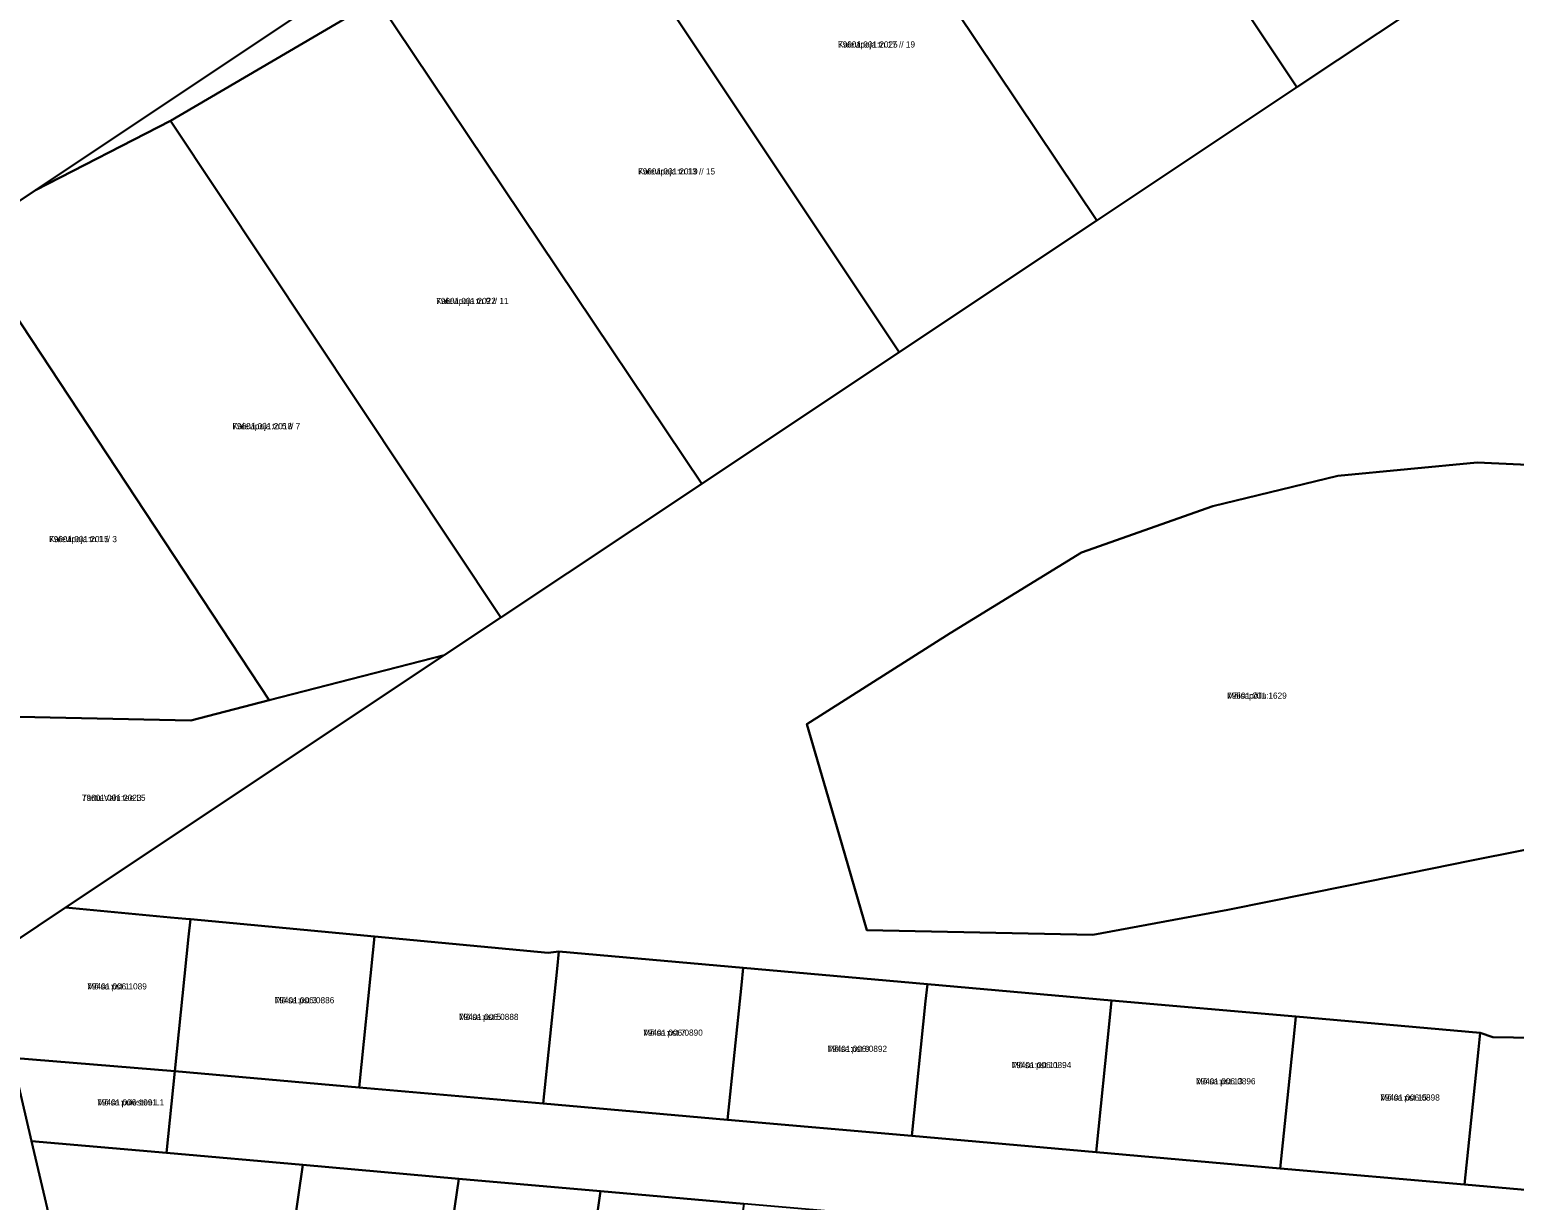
# Model space of a CAD drawing. Extents: x 625111 to 706696, y 6474150 to 6504223.
# Drawn here: x 659027.1 to 659388.4, y 6477250.5 to 6477535.3 of the extents above; entities that cross this region are included whole.
import ezdxf

# ---------------------------------------------------------------- set-up
doc = ezdxf.new("R2010")
doc.units = 0
for name, color, linetype in [('L_AADRESS', 7, 'Continuous'), ('PIIR', 7, 'Continuous'), ('TUNNUS', 7, 'Continuous')]:
    doc.layers.add(name, color=color, linetype=linetype)

msp = doc.modelspace()

# ---------------------------------------------------------------- linework, layer by layer
at = {"layer": 'PIIR'}
for points in [[(659232.49, 6477793.03), (659251.76, 6477778.82), (659253.39, 6477777.62), (659345.56, 6477707.61), (659341.25, 6477704.74), (659028.54, 6477496.24), (659011.15, 6477484.64), (658978.33, 6477462.76), (658893.64, 6477716.85), (658906.78, 6477751.79), (658969.42, 6477781.01), (659162.31, 6477839.01), (659167.55, 6477840.54), (659168.77, 6477839.47), (659176.76, 6477833.75), (659193.86, 6477821.51)], [(659028.54, 6477496.24), (659341.25, 6477704.74), (659345.56, 6477707.61), (659353.33, 6477701.7), (659348.84, 6477698.71), (659339.23, 6477692.3), (659307.13, 6477670.9), (659257.71, 6477637.96), (659208.73, 6477605.29), (659160.85, 6477573.67), (659111.66, 6477542.61), (659061.4, 6477513.14)], [(659257.71, 6477637.96), (659307.13, 6477670.9), (659384.93, 6477554.2), (659335.49, 6477521.28)], [(659208.73, 6477605.29), (659257.71, 6477637.96), (659335.49, 6477521.28), (659286.78, 6477488.84)], [(659160.85, 6477573.67), (659208.73, 6477605.29), (659286.78, 6477488.84), (659238.68, 6477456.8)], [(659111.66, 6477542.61), (659160.85, 6477573.67), (659238.68, 6477456.8), (659190.69, 6477424.84)], [(659061.4, 6477513.14), (659111.66, 6477542.61), (659190.69, 6477424.84), (659141.77, 6477392.27)], [(659011.15, 6477484.64), (659028.54, 6477496.24), (659061.4, 6477513.14), (659141.77, 6477392.27), (659128, 6477383.1), (659085.37, 6477372.16)], [(658978.33, 6477462.76), (659011.15, 6477484.64), (659085.37, 6477372.16), (659066.32, 6477367.26), (659016.87, 6477368.25), (659003.37, 6477387.46)], [(659216.21, 6477366.34), (659224.06, 6477339.44), (659230.84, 6477316.19), (659285.85, 6477315.08), (659318.68, 6477321.16), (659348.02, 6477327.11), (659377.96, 6477333.14), (659401.27, 6477337.81), (659406.94, 6477338.94), (659417.81, 6477428.24), (659412.69, 6477428.47), (659379.35, 6477429.97), (659345.4, 6477426.74), (659315.02, 6477419.4), (659283.04, 6477408.07), (659251.14, 6477388.49)], [(659224.06, 6477339.44), (659216.21, 6477366.34), (659251.14, 6477388.49), (659283.04, 6477408.07), (659315.02, 6477419.4), (659345.4, 6477426.74), (659379.35, 6477429.97), (659412.69, 6477428.47), (659417.81, 6477428.24), (659406.94, 6477338.94), (659401.27, 6477337.81), (659377.96, 6477333.14), (659348.02, 6477327.11), (659318.68, 6477321.16), (659285.85, 6477315.08), (659230.84, 6477316.19)], [(659035.81, 6477321.69), (659015.77, 6477308.37), (659002.48, 6477356.08), (658992.28, 6477386.97), (659016.87, 6477368.25), (659066.32, 6477367.26), (659085.37, 6477372.16), (659128, 6477383.1)], [(659065.79, 6477314.62), (659062.43, 6477281.9), (659022.88, 6477285.14), (659015.77, 6477308.37), (659035.81, 6477321.69), (659061.4, 6477319.31), (659065.14, 6477318.97), (659066.23, 6477318.87)], [(659110.63, 6477310.69), (659107.27, 6477277.96), (659062.43, 6477281.9), (659065.79, 6477314.62), (659066.23, 6477318.87), (659076.62, 6477317.94), (659111.03, 6477314.7)], [(659155.46, 6477306.77), (659152.1, 6477274.02), (659107.27, 6477277.96), (659110.63, 6477310.69), (659111.03, 6477314.7), (659153.27, 6477310.72), (659155.9, 6477310.99)], [(659200.3, 6477302.85), (659196.93, 6477270.08), (659152.1, 6477274.02), (659155.46, 6477306.77), (659155.9, 6477310.99), (659200.73, 6477307.06)], [(659245.13, 6477298.92), (659241.76, 6477266.14), (659196.93, 6477270.08), (659200.3, 6477302.85), (659200.73, 6477307.06), (659245.57, 6477303.09)], [(659289.96, 6477295), (659286.59, 6477262.2), (659241.76, 6477266.14), (659245.13, 6477298.92), (659245.57, 6477303.09), (659290.38, 6477299.14)], [(659334.8, 6477291.08), (659331.43, 6477258.26), (659286.59, 6477262.2), (659289.96, 6477295), (659290.38, 6477299.14), (659335.23, 6477295.17)], [(659379.63, 6477287.15), (659376.26, 6477254.32), (659331.43, 6477258.26), (659334.8, 6477291.08), (659335.23, 6477295.17), (659380.03, 6477291.23)], [(659415.36, 6477283.25), (659410.25, 6477251.33), (659376.26, 6477254.32), (659379.63, 6477287.15), (659380.03, 6477291.23), (659383.12, 6477290.18), (659393.2, 6477290.01), (659400.9, 6477289.36), (659416.13, 6477288.02)], [(659062.43, 6477281.9), (659060.39, 6477262), (659027.61, 6477264.87), (659022.88, 6477285.14)], [(659093.63, 6477259.08), (659088.92, 6477226.55), (659034.62, 6477234.89), (659027.61, 6477264.87), (659060.39, 6477262)], [(659131.55, 6477255.75), (659126.48, 6477220.78), (659088.92, 6477226.55), (659093.63, 6477259.08)], [(659166.04, 6477252.72), (659160.66, 6477215.53), (659126.48, 6477220.78), (659131.55, 6477255.75)], [(659200.88, 6477249.65), (659195.17, 6477210.23), (659160.66, 6477215.53), (659166.04, 6477252.72)]]:
    msp.add_lwpolyline(points, close=True, dxfattribs=at)
for points in [[(659393.2, 6477290.01), (659383.12, 6477290.18), (659380.03, 6477291.23), (659335.23, 6477295.17), (659290.38, 6477299.14), (659245.57, 6477303.09), (659200.73, 6477307.06), (659155.9, 6477310.99), (659153.27, 6477310.72), (659111.03, 6477314.7), (659076.62, 6477317.94), (659066.23, 6477318.87), (659065.14, 6477318.97), (659061.4, 6477319.31), (659035.81, 6477321.69), (659128, 6477383.1), (659141.77, 6477392.27), (659190.69, 6477424.84), (659238.68, 6477456.8), (659286.78, 6477488.84), (659335.49, 6477521.28), (659384.93, 6477554.2)], [(659022.88, 6477285.14), (659027.61, 6477264.87), (659034.62, 6477234.89), (659046.22, 6477185.21), (659054.92, 6477147.94), (659058.14, 6477134.15), (659072.57, 6477072.34), (659083.27, 6477026.56), (659093.96, 6476980.77), (659119.09, 6476873.18), (659130.63, 6476823.75), (659145.22, 6476761.27), (659156.03, 6476714.99), (659137.78, 6476720.47), (659111.23, 6476832.81), (659041.31, 6477128.02), (659034.25, 6477157.62), (659034.75, 6477157.58), (659008.22, 6477269.11)], [(659407.08, 6477231.53), (659377.48, 6477234.13), (659349.54, 6477236.59), (659321.6, 6477239.04), (659292.67, 6477241.59), (659262.74, 6477244.22), (659231.81, 6477246.94), (659200.88, 6477249.65), (659166.04, 6477252.72), (659131.55, 6477255.75), (659093.63, 6477259.08), (659060.39, 6477262), (659062.43, 6477281.9), (659107.27, 6477277.96), (659152.1, 6477274.02), (659196.93, 6477270.08), (659241.76, 6477266.14), (659286.59, 6477262.2), (659331.43, 6477258.26), (659376.26, 6477254.32), (659410.25, 6477251.33)]]:
    msp.add_lwpolyline(points, dxfattribs=at)

# ---------------------------------------------------------------- texts
at = {"layer": 'L_AADRESS'}
for s, p in [('Kalevipoja tn 17 // 19', (659223.82, 6477530.95)), ('Kalevipoja tn 13 // 15', (659175.17, 6477500.07)), ('Kalevipoja tn 9 // 11', (659126.04, 6477468.55)), ('Kalevipoja tn 5 // 7', (659076.46, 6477438.08)), ('Kalevipoja tn 1 // 3', (659031.85, 6477410.61)), ('Mõisapõllu', (659318.5, 6477372.52)), ('Tartu-Vahi tee L5', (659039.82, 6477347.67)), ('Mõisa pst 1', (659041.13, 6477301.79)), ('Mõisa pst 3', (659086.75, 6477298.42)), ('Mõisa pst 5', (659131.57, 6477294.36)), ('Mõisa pst 7', (659176.41, 6477290.53)), ('Mõisa pst 9', (659221.25, 6477286.6)), ('Mõisa pst 11', (659266.07, 6477282.65)), ('Mõisa pst 13', (659310.91, 6477278.7)), ('Mõisa puiestee L1', (659043.58, 6477273.57)), ('Mõisa pst 15', (659355.74, 6477274.75))]:
    msp.add_text(s, height=1.5, dxfattribs=at).set_placement(p)
at = {"layer": 'TUNNUS'}
for s, p in [('79601:001:2025', (659223.82, 6477530.95)), ('79601:001:2019', (659175.17, 6477500.07)), ('79601:001:2022', (659126.04, 6477468.55)), ('79601:001:2018', (659076.46, 6477438.08)), ('79601:001:2015', (659031.85, 6477410.61)), ('79601:001:1629', (659318.5, 6477372.52)), ('79601:001:2023', (659039.82, 6477347.67)), ('79401:006:1089', (659041.13, 6477301.79)), ('79401:006:0886', (659086.75, 6477298.42)), ('79401:006:0888', (659131.57, 6477294.36)), ('79401:006:0890', (659176.41, 6477290.53)), ('79401:006:0892', (659221.25, 6477286.6)), ('79401:006:0894', (659266.07, 6477282.65)), ('79401:006:0896', (659310.91, 6477278.7)), ('79401:006:1091', (659043.58, 6477273.57)), ('79401:006:0898', (659355.74, 6477274.75))]:
    msp.add_text(s, height=1.5, dxfattribs=at).set_placement(p)

doc.saveas('drawing.dxf')
